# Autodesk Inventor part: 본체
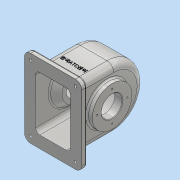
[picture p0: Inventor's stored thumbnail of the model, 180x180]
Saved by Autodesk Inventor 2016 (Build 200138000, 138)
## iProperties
Created: 2018-08
Part Number: 본체
Material: 알루미늄 6061
Document SubType Name: Modeling
Designer: Administrator
Density: 2.7 g/cm^3
Appearance: 알루미늄 - 평지
Mass: 1091.75 g
Surface Area: 1182.51 cm^2
Volume: 404.352 cm^3
Author: Administrator
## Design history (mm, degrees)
sketch "스케치1"
  geometry: L1 (-55, -75)-(55, -75); L2 (55, -75)-(55, 75); L3 (55, 75)-(-55, 75); L4 (-55, 75)-(-55, -75); L5 (-55, -75)-(55, 75); L6 (55, -75)-(-55, 75); 1 further point
  constraints: 12 end point, 2 midpoint, 2 parallel, 1 horizontal, 1 perpendicular
  dimensions: "d0" = 110 distance of L3.end L2.end; "d1" = 150 distance of L2.end L1.end
extrude "돌출1" new body sketch "스케치1" distance "d2" = 10; taper "d3" = 0 deg
sketch "스케치2"
  geometry: L1 (0, -75)-(0, 75) reference; L2 (78, 58)-(0, 58); L3 (78, -58)-(0, -58); L4 (0, -75)-(0, 75) reference; L5 (0, 75)-(10, 75) reference; L6 (10, -75)-(10, 75) reference; L7 (0, -75)-(10, -75) reference; L8 (78, 0)-(78, 21); L9 (0, 58)-(0, -58); A1 r 58 centre (78, 0) between (78, -58) and (78, 58); 3 further points
  constraints: 8 end point, 2 midpoint, 2 point on circle, 2 point on line, 2 vertical alignment, 1 centre point, 1 collinear, 1 horizontal, 1 horizontal alignment, 1 perpendicular, 1 vertical
  dimensions: "d4" = 78 distance from line of L1 L8.start; "d5" = 116 diameter of A1; "d7" = 75 distance from line of L8.start L5 (derived)
extrude "돌출2" join sketch "스케치2" stored distance "d8" = 77; taper "d9" = 0 deg
feature "쉘1" dims "d10" = 10, "d11" = 5, "d122" = 6
fillet "모깎기1" dims "d12" = 13
fillet "모깎기2" dims "d13" = 8
sketch "스케치4"
  geometry: L1 (-116, 65)-(89, 65); L2 (55, 0)-(-55, 0) reference; L3 (-43.5, 65)-(-43.5, 103); L4 (-43.5, 103)-(-31.418, 103); L5 (-31.418, 103)-(-19.5, 93); L6 (-19.5, 93)-(-19.5, 65); L7 (-43.5, 65)-(-19.5, 65); L8 (-38.5, 78)-(-38.5, 123) reference; 1 further point
  constraints: 12 end point, 2 perpendicular, 2 point on line, 1 collinear, 1 horizontal, 1 vertical
  dimensions: "d14" = 65 distance between parallel lines of L2 L1; "d15" = 5 distance between parallel lines of L8 L3; "d16" = 24 distance between parallel lines of L6 L3; "d17" = 50 deg angle of L6 L5; "d18" = 56 diameter of L5.end L1; "d19" = 76 diameter of L4 L1
revolve "회전1" sketch "스케치4" stored, may be unused: angle "d20" = 90 deg
node "작업 평면1"
sketch "스케치5"
  geometry: L1 (75, 0)-(-75, 0) reference; C1 r 38 at (0, 65); 2 further points
  constraints: 1 centre point, 1 midpoint, 1 vertical alignment
  dimensions: "d22" = 76 diameter of C1; "d23" = 65 distance from line of L1 C1.centre
extrude "돌출3" join sketch "스케치5" stored distance "d24" = 77; taper "d25" = 0 deg
hole "구멍1" diameter "d28" = 40; stored, may be unused: countersink angle "d32" = 90 deg, drill point angle "d34" = 118 deg; dims "d26" = 10, "d27" = 10, "d29" = 6, "d30" = 4, "d31" = 2, "d33" = 8
node "작업 평면2"
sketch "스케치6"
  geometry: L1 (-55, -75)-(-55, 75) reference; L2 (-55, 75)-(55, 75) reference; L3 (55, -75)-(-55, -75) reference; C1 r 6 at (0, 0); 1 further point
  constraints: 1 centre point
  dimensions: "d36" = 12 diameter of C1; "d37" = 55 distance from line of C1.centre L1; "d39" = 75 distance from line of C1.centre L3
extrude "돌출4" join sketch "스케치6" stored distance "d40" = 77; taper "d41" = 5 deg
hole "구멍2" diameter "d44" = 4.459; stored, may be unused: countersink angle "d48" = 90 deg, drill point angle "d50" = 118 deg; dims "d42" = 10, "d43" = 10, "d45" = 10, "d46" = 4, "d47" = 2, "d49" = 12.8
sketch "스케치7"
  geometry: L1 (-29.5, -78)-(80.5, -78) reference; L2 (-13, 0)-(-13, -68) reference; 2 further points
  constraints: 1 other
  dimensions: "d51" = 40 distance from line of L1 point (25.5, -38); "d52" = 38.5 distance from line of point (25.5, -38) L2
feature "엠보싱1" sketch "스케치7" dims "d0" = 110, "d1" = 150, "d4" = 78, "d5" = 116, "d7" = 75 (derived), "d53" = 0.5, "d54" = 0
fillet "모깎기3" dims "d55" = 12
hole "구멍3" diameter "d58" = 5; stored, may be unused: countersink angle "d62" = 90 deg, drill point angle "d64" = 118 deg; dims "d56" = 10, "d57" = 10, "d59" = 10, "d60" = 12, "d61" = 4, "d63" = 12.8
hole "구멍4" diameter "d67" = 5; stored, may be unused: countersink angle "d71" = 90 deg, drill point angle "d73" = 118 deg; dims "d65" = 10, "d66" = 10, "d68" = 10, "d69" = 12, "d70" = 4, "d72" = 12.8
hole "구멍5" diameter "d76" = 5; stored, may be unused: countersink angle "d80" = 90 deg, drill point angle "d82" = 118 deg; dims "d74" = 10, "d75" = 10, "d77" = 10, "d78" = 12, "d79" = 4, "d81" = 12.8
hole "구멍6" diameter "d85" = 5; stored, may be unused: countersink angle "d89" = 90 deg, drill point angle "d91" = 118 deg; dims "d83" = 10, "d84" = 10, "d86" = 10, "d87" = 12, "d88" = 4, "d90" = 12.8
fillet "모깎기4" dims "d92" = 3
fillet "모깎기5" dims "d93" = 3
chamfer "모따기1" distance "d94" = 1; stored, may be unused: second distance "d95" = 2, angle "d96" = 45 deg
sketch "스케치8"
  geometry: C1 r 38 at (0, 0) reference; C2 r 21 at (0, 0) reference; 5 further points
  constraints: 1 vertical alignment, 5 other
  dimensions: "d97" = 29 distance of C1.centre point (0, 29); "d100" = 360 deg dimension on C1.centre point (0, 29) (derived)
hole "구멍7" sketch "스케치8" at (0, 29), (-29, 0), (0, -29), (29, 0) diameter "d102" = 3.242; stored, may be unused: countersink angle "d106" = 90 deg, drill point angle "d108" = 118 deg; dims "d103" = 8, "d104" = 12, "d105" = 4, "d107" = 10
sketch "스케치9"
  geometry: C1 r 28 at (0, 0) reference; 5 further points
  constraints: 1 vertical alignment, 5 other
  dimensions: "d109" = 29 distance of C1.centre point (0, 29); "d112" = 360 deg dimension on C1.centre point (0, 29) (derived)
hole "구멍8" sketch "스케치9" at (0, 29), (-29, 0), (0, -29), (29, 0) diameter "d114" = 3.242; stored, may be unused: countersink angle "d118" = 90 deg, drill point angle "d120" = 118 deg; dims "d115" = 8, "d116" = 12, "d117" = 4, "d119" = 10
fillet "모깎기6" dims "d121" = 3
sketch "스케치10"
  geometry: L1 (-76, 156)-(87, 156); L2 (87, 156)-(87, -21); L3 (87, -21)-(-76, -21); L4 (-76, -21)-(-76, 156); 1 further point
  constraints: 8 end point, 2 parallel, 1 horizontal, 1 perpendicular
extrude "돌출5" cut sketch "스케치10" stored distance "d123" = 10; taper "d124" = 0 deg
node "솔리드1"
node "투영된 루프1"
node "투영된 루프2"
other parameters: "d21" = -87, "d35" = -142
